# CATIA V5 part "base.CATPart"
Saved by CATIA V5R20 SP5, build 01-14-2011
Part number: base
Publications: "Plan.6"
Bounding box of the stored display mesh (mm): x -325 to 325, y -180 to 250, z 20 to 105
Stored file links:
  D:\Dropbox\Pack 1 sylvain\mmoreau\mmoreau\mmoreau\fin\base.CATPart
  U:\think motion\fin\think motion2.CATProduct
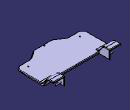
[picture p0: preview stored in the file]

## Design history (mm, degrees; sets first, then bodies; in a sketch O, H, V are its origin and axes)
External parameters (linked from other documents)
  `External.écartement jambe` = 650 mm
  `External.hauteur roues ar` = 40 mm
  `External.éloignement roues ar` = 220 mm
  `External.décalage poche pour jambe` = 10 mm
Set1
  Plane1 to Plane3: linked copy from another document
  Point1: linked copy from another document
  Plane4: linked copy from another document
  Plane5: linked copy from another document
  Point2 to Point4: linked copy from another document
Set2
  Plane6: type 2Lines, Element1 edge [face of Pad1 from Sketch1.L1 | face of Pad1 from Sketch1.L10], Element2 edge [face of Fillet2 | face of Pad1 from Sketch1.L10]
Body1 (main body)
  Sketch1 on Plane1, origin (0, 0, 40), H (1, 0, 0), V (0, 1, 0)
    line L1 (0, -180) -> (-89.3111, -180)
    point P1 (0, -180)
    point P2 (-89.3111, -180)
    line L2 (-89.3111, -180) -> (-175, -120)
    point P3 (-175, -120)
    line L3 (-175, -120) -> (-325, -120)
    point P4 (-325, -120)
    line L4 (-325, -120) -> (-325, 150)
    point P5 (-325, 150)
    line L5 (-325, 150) -> (0, 150)
    point P6 (0, 150)
    point P7 (0, 150)
    point P8 (325, 150)
    line L6 (325, 150) -> (0, 150)
    point P9 (325, -120)
    line L7 (325, -120) -> (325, 150)
    point P10 (175, -120)
    line L8 (175, -120) -> (325, -120)
    point P11 (89.3111, -180)
    line L9 (89.3111, -180) -> (175, -120)
    point P12 (0, -180)
    line L10 (0, -180) -> (89.3111, -180)
    distance L1 H = 180
    distance L4 V = 325 {= `External.écartement jambe` /2}
    angle L2 L1 = 145
    distance L3 L1 = 60
    length L3 = 150
    distance L5 H = 150
    horizontal: L1 H, L3 H, L5 H
    coincidence: P1 V, P6 V, P1 P12, P6 P7
    vertical: L4 V
    symmetry: P6 P7 V, P5 P8 V, L5 L6 V, P4 P9 V, L4 L7 V, P3 P10 V, L3 L8 V, P2 P11 V, L2 L9 V, P1 P12 V, L1 L10 V
  Pad1: profile Sketch1, direction (0, 0, -1), length 20
  Sketch2 on Plane2, origin (-325, 0, 0), H (0, 1, 0), V (0, 0, 1)
    line L1 (144.2265, 40) -> (181.7543, 105)
    point P1 (144.2265, 40)
    line L2 (181.7543, 105) -> (250, 105)
    line L3 (250, 105) -> (250, 90)
    line L4 (250, 90) -> (190.4145, 90)
    line L5 (190.4145, 90) -> (150, 20)
    point P6 (150, 20)
    reference projected line E1 (150, 40) -> (-120, 40) from edge [face of Pad1 from Sketch1.L4 | start face of Pad1]
    reference projected point E2 (150, 20) from vertex [face of Pad1 from Sketch1.L4 | end face of Pad1 | face of Pad1 from Sketch1.L5]
    line L6 (144.2265, 40) -> (150, 20)
    point P7 (144.2265, 40)
    reference projected point E3 (220, 40) from Point1
    distance L4 L2 = 15
    distance L5 L1 = 15
    angle L5 L4 = 120
    distance L4 E3 = 50 {= `External.hauteur roues ar` +10mm}
    distance L3 V = 250 {= `External.éloignement roues ar` +30mm}
    horizontal: L2 H, L4 H
    vertical: L3 V
    coincidence: P1 E1, P6 E2, P7 L1, P7 P1
  Pad2: profile Sketch2, direction (1, 0, 0), up to Plane4
  Sketch3 on Plane3, origin (325, 0, 0), H (0, 1, 0), V (0, 0, 1)
    line L1 (144.2265, 40) -> (181.7543, 105)
    point P1 (144.2265, 40)
    line L2 (181.7543, 105) -> (250, 105)
    line L3 (250, 105) -> (250, 90)
    line L4 (250, 90) -> (190.4145, 90)
    line L5 (190.4145, 90) -> (150, 20)
    point P6 (150, 20)
    reference projected line E1 (150, 40) -> (-120, 40) from edge [face of Pad1 from Sketch1.L4 | start face of Pad1]
    reference projected point E2 (150, 20) from vertex [face of Pad1 from Sketch1.L4 | end face of Pad1 | face of Pad1 from Sketch1.L5]
    line L6 (144.2265, 40) -> (150, 20)
    point P7 (144.2265, 40)
    reference projected point E3 (220, 40) from Point1
    distance L4 L2 = 15
    distance L5 L1 = 15
    angle L5 L4 = 120
    distance L4 E3 = 50 {= `External.hauteur roues ar` +10mm}
    distance L3 V = 250 {= `External.éloignement roues ar` +30mm}
    horizontal: L2 H, L4 H
    vertical: L3 V
    coincidence: P1 E1, P6 E2, P7 L1, P7 P1
  Pad3: profile Sketch3, direction (-1, 0, 0), up to Plane5
  Sketch4 on end face of Pad2, origin (-225, 0, 0), H (0, 1, 0), V (0, 0, 1)
    line L1 (181.7543, 105) -> (132.6795, 20)
    point P2 (132.6795, 20)
    line L2 (181.7543, 105) -> (250, 105)
    line L3 (250, 105) -> (250, 20)
    line L4 (250, 20) -> (132.6795, 20)
    point P5 (132.6795, 20)
    reference projected line E1 (250, 105) -> (181.7543, 105) from edge [face of Pad3 from Sketch3.L2 | start face of Pad3]
    reference projected line E2 (181.7543, 105) -> (144.2265, 40) from edge [face of Pad3 from Sketch3.L1 | face of Pad3]
    reference projected line E3 (-120, 20) -> (150, 20) from edge [end face of Pad1 | face of Pad3]
    reference projected line E4 (250, 90) -> (250, 105) from edge [face of Pad3 from Sketch3.L3 | start face of Pad3]
    horizontal: L2 H
    vertical: L3 V
    coincidence: P5 L1, L2 E1, L1 E2, L4 E3, P2 P5, E4 L3
  Pad4: profile Sketch4, direction (1, 0, 0), length 10
  Sketch5 on end face of Pad3, origin (225, 0, 0), H (0, 1, 0), V (0, 0, 1)
    line L1 (181.7543, 105) -> (132.6795, 20)
    point P2 (132.6795, 20)
    line L2 (181.7543, 105) -> (250, 105)
    line L3 (250, 105) -> (250, 20)
    line L4 (250, 20) -> (132.6795, 20)
    point P5 (132.6795, 20)
    reference projected line E1 (250, 105) -> (181.7543, 105) from edge [face of Pad3 from Sketch3.L2 | start face of Pad3]
    reference projected line E2 (181.7543, 105) -> (144.2265, 40) from edge [face of Pad3 from Sketch3.L1 | face of Pad3]
    reference projected line E3 (-120, 20) -> (150, 20) from edge [end face of Pad1 | face of Pad3]
    reference projected line E4 (250, 90) -> (250, 105) from edge [face of Pad3 from Sketch3.L3 | start face of Pad3]
    horizontal: L2 H
    vertical: L3 V
    coincidence: P5 L1, L2 E1, L1 E2, L4 E3, P2 P5, E4 L3
  Pad5: profile Sketch5, direction (-1, 0, 0), length 10
  Sketch6 on start face of Pad4, origin (-225, 0, 0), H (0, -1, 0), V (0, 0, 1)
    circle A1 centre (-220, 40) radius 5
    point P1 (-220, 40)
    reference projected point E1 (-220, 40) from Point1
    radius A1 = 5
    coincidence: E1 P1
  Pad6: profile Sketch6, direction (-1, 0, 0), length 50
  Sketch7 on start face of Pad5, origin (225, 0, 0), H (0, -1, 0), V (0, 0, 1)
    circle A1 centre (-220, 40) radius 5
    point P1 (-220, 40)
    reference projected point E1 (-220, 40) from Point1
    radius A1 = 5
    coincidence: P1 E1
  Pad7: profile Sketch7, direction (1, 0, 0), length 50
  Fillet1: radius 50, on edge [face of Pad1 | face of Pad1 from Sketch1.L3]; edge [start face of Pad1 | face of Pad4]; edge [face of Pad4 | face of Pad4]; edge [face of Pad1 from Sketch1.L3 | face of Pad1 from Sketch1.L2]; edge [face of Pad1 from Sketch1.L2 | face of Pad1 from Sketch1.L1]; edge [face of Pad1 from Sketch1.L10 | face of Pad1 from Sketch1.L9]; edge [face of Pad1 from Sketch1.L9 | face of Pad1 from Sketch1.L8]; edge [face of Pad1 from Sketch1.L8 | face of Pad1]; edge [face of Pad5 | start face of Pad1]; edge [face of Pad5 | face of Pad5]
  Fillet2: radius 5, on edge [face of Pad5 | face of Pad5]; edge [face of Pad3 from Sketch3.L4 | face of Pad5]; edge [face of Pad5 | start face of Pad5] (x2); edge [end face of Pad5 | face of Pad5] (x3); edge [face of Pad5 | face of Pad1] (x2); edge [face of Pad3 from Sketch3.L4 | face of Pad1]; edge [face of Pad3 from Sketch3.L5 | face of Pad1]; edge [face of Pad1 | start face of Pad1]; edge [face of Pad4 | face of Pad4]; edge [face of Pad4 | face of Pad2 from Sketch2.L4]; edge [start face of Pad4 | face of Pad4]; edge [face of Pad4 | end face of Pad4] (x2); edge [face of Pad1 | face of Pad2 from Sketch2.L5]; edge [face of Pad1 | face of Pad2 from Sketch2.L4]; edge [face of Pad1 from Sketch1.L5 | start face of Pad1]; edge [face of Pad5 | face of Pad1 from Sketch1.L6]; edge [face of Pad5 | end face of Pad4]
  Sketch8 on Plane1, origin (0, 0, 40), H (1, 0, 0), V (0, 1, 0)
    point P1 (-200, -30)
    line L1 (-200, -30) -> (-385.3348, -30)
    line L2 (-385.3348, -30) -> (-385.3348, -158.4106)
    line L3 (-385.3348, -158.4106) -> (-200, -158.4106)
    line L4 (-200, -158.4106) -> (-200, -30)
    point P2 (-385.3348, -30)
    point P3 (-385.3348, -158.4106)
    point P4 (-200, -158.4106)
    point P5 (200, -158.4106)
    point P6 (385.3348, -158.4106)
    line L5 (385.3348, -158.4106) -> (200, -158.4106)
    point P7 (385.3348, -30)
    line L6 (385.3348, -30) -> (385.3348, -158.4106)
    point P8 (200, -30)
    line L7 (200, -30) -> (385.3348, -30)
    line L8 (200, -158.4106) -> (200, -30)
    distance L4 V = 200
    distance L1 H = 30
    horizontal: L1 H, L3 H
    vertical: L2 V, L4 V
    symmetry: P4 P5 V, P3 P6 V, L3 L5 V, P2 P7 V, L2 L6 V, P1 P8 V, L1 L7 V, L4 L8 V
  Pocket1: profile Sketch8, direction (0, 0, -1), length 105, opposite side length -10 {= -`External.décalage poche pour jambe`}
  Fillet3: radius 20, on edge [face of Pocket1 from Sketch8.L8 | face of Pocket1 from Sketch8.L7]; edge [face of Pocket1 from Sketch8.L1 | face of Pocket1 from Sketch8.L4]
  Sketch9 on start face of Pocket1, origin (295.868, -74.8479, 30), H (1, 0, 0), V (0, -1, 0)
    point P1 (-45.868, -4.8479)
    reference projected point E1 (-45.868, -4.8479) from Point3
    coincidence: P1 E1
  Hole1: placed by Sketch9, at (250, -70, 30) direction (0, 0, 1), diameter 10, through (limit type 3)
  Sketch10 on start face of Pad1, origin (-205.0748, -68.9924, 40), H (1, 0, 0), V (0, 1, 0)
    point P1 (-44.9252, -1.0076)
    reference projected point E1 (-44.9252, -1.0076) from Point4
    coincidence: P1 E1
  Hole2: placed by Sketch10, at (-250, -70, 40) direction (0, 0, -1), diameter 10, through (limit type 3)
  Sketch11 on start face of Pad1, origin (-64.3303, -150.6964, 40), H (1, 0, 0), V (0, 1, 0)
    point P1 (64.3303, -14.3036)
    reference intersected line E1 through (64.3303, 0) direction (0, 1) from yz-plane
    reference intersected line E2 through (0, 150.6964) direction (-1, 0) from zx-plane
    distance P1 E1 = 0
    distance P1 E2 = 165
  Hole3: placed by Sketch11, at (0, -165, 40) direction (0, 0, -1), diameter 10, through (limit type 3)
